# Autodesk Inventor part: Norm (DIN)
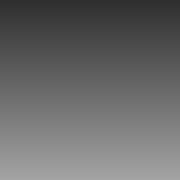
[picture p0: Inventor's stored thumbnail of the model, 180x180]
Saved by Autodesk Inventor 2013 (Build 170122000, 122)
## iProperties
Created: 2012-02
Part Number: Norm (DIN)
Material: Allgemein
Document SubType Name: Modeling
Designer: x86 deu
Density: 1 g/cm^3
Author: x86 deu
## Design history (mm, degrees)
